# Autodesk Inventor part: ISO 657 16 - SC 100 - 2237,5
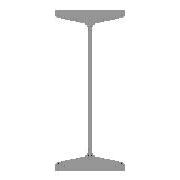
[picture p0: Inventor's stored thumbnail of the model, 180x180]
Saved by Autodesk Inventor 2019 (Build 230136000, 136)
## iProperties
_CCFamilyMember: 1
_CCFamilyDisplayName: ISO 657/16 - 1980 - Poutres en acier laminées à chaud - Partie 16: profilés en H (série métrique) - Cotes et propriétés de section
_FrameMemberDoc: Frame Member File
_Version: 15.0.0
_GetPNFromCC: 1
Created: 2018-01
Part Number: ISO 657 16 - SC 100 - 2237,5
Material: Acier, doux
Description: Poutres en acier laminées à chaud - Partie 16: profilés en H (série métrique) - Cotes et propriétés de section
Document SubType Name: Modeling
Standard: ISO
Designer: Fabian Perrée
Standard Revision: First edition 1980-02-15
Standards Organization: ISO
Language: fr-FR
Size Designation: SC 100
Categories: <MemberInstance><Categories><Category DisplayName="Profilés" InternalName="089c4875-fa83-4c05-b084-43b9cc11f5ed" Mnemonic="GRDR"><CategoryParameter DisplayName=
Stock Number: SC 100
Density: 7.85 g/cm^3
Appearance: Semi-poli
Mass: 44309.5 g
Surface Area: 12051.7 cm^2
Volume: 5644.52 cm^3
IsCustomPart: 1
G_W: 100,000 mm
G_H: 100,000 mm
+A54BEF43-0FA8-4A60-B2B6-B0B0D511939D+DETAILDECOUPE1: Angle de coupe 90,00 deg
G_L: 2237,500 mm
+E90C5402-4D48-4B32-A015-53D85A7B4022+DETAILDECOUPE4: Angle de coupe 67,38 deg
Author: Fabian Perrée
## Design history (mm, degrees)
node "Plan de départ"
node "Plan de fin"
sketch "Esquisse"
  geometry: L1 (-3, 0)-(-3, -26.266); L2 (-13.33, -38.149)-(-44.835, -42.577); L3 (-50, -48.518)-(-50, -50); L4 (-50, -50)-(0, -50); L5 (-26.5, -50)-(-26.5, -40); L6 (-61.333, 0)-(81.777, 0); L7 (0, 0)-(0, -50); L8 (0, -60)-(0, 80); L9 (3, 0)-(3, -26.266); L10 (13.33, -38.149)-(44.835, -42.577); L11 (50, -48.518)-(50, -50); L12 (50, -50)-(0, -50); L13 (-3, 0)-(0, 0); L14 (-3, 0)-(-3, 26.266); L15 (-13.33, 38.149)-(-44.835, 42.577); L16 (-50, 48.518)-(-50, 50); L17 (-50, 50)-(0, 50); L18 (50, 48.518)-(50, 50); L19 (13.33, 38.149)-(44.835, 42.577); L20 (3, 0)-(3, 26.266); L21 (50, 50)-(0, 50); L22 (0, 108)-(0, -88) reference; L23 (-89.955, 0)-(110.399, 0) reference; A1 r 6 centre (-44, 48.518) between (-50, 48.518) and (-44.835, 42.577); A2 r 6 centre (44, 48.518) between (44.835, 42.577) and (50, 48.518); A3 r 6 centre (44, -48.518) between (50, -48.518) and (44.835, -42.577); A4 r 6 centre (-44, -48.518) between (-44.835, -42.577) and (-50, -48.518); A5 r 12 centre (-15, 26.266) between (-3, 26.266) and (-13.33, 38.149); A6 r 12 centre (15, 26.266) between (13.33, 38.149) and (3, 26.266); A7 r 12 centre (15, -26.266) between (3, -26.266) and (13.33, -38.149); A8 r 12 centre (-15, -26.266) between (-13.33, -38.149) and (-3, -26.266); 14 further points
  constraints: 42 end point, 24 point on line, 17 symmetric about line, 16 point on circle, 16 tangent, 8 centre point, 6 equal radius, 4 collinear, 2 perpendicular, 12 other
  dimensions: "d1" = 10 vertical distance of L3.end L5.end (= G_T1); "d2" = 23.5 distance between parallel lines of L5 L3 (= -0.25 x G_T + 0.25 x G_W); "d3" = 3 distance between parallel lines of L1 L7 (= 0.5 x G_T); "d4" = 50 distance between parallel lines of L7 L3 (= 0.5 x G_W); "d9" = 50 distance from line of L1.start L4 (= 0.5 x G_H); "d14" = 98 deg angle of L2 L1 (= G_NG); "d15" = 6 radius of A1 (= G_ER); "d16" = 12 radius of A5 (= G_IR)
extrude "Corps" new body sketch "Esquisse" stored distance "d5" = 2237.5 (= G_L); taper "d6" = 0 deg
node "Driven Length"
  sketch "Sketch3"
    geometry: L1 (0, 0)-(10, 0) reference
    constraints: 2 end point, 1 horizontal
  workplane "Work Plane3"
  sketch "Sketch4"
    geometry: L1 (-2, 50)-(12, 50) reference; L2 (-2, 2287.5)-(12, 2287.5) reference
    dimensions: "d20" = 2237.5 distance between parallel lines of L1 L2 (derived)
node "Plan de construction4"
feature "Scission1"
node "Plan de construction7"
feature "Scission4"
body "Solid1"
other parameters: "G_W" = 100 (= G_H) [user parameter; used in 2 equation terms], "G_H" = 100 [user parameter; used in 2 equation terms], "G_T" = 6 [user parameter; used in 2 equation terms], "G_T1" = 10 [user parameter; used in 1 equation term], "G_L" = 2237.5 (= d20) [user parameter; used in 1 equation term], "G_ER" = 6 [user parameter; used in 1 equation term], "G_IR" = 12 [user parameter; used in 1 equation term], "G_NG" = 98 deg [user parameter; used in 1 equation term], "G_OFFSET_END" = -87.5 [user parameter; used in 1 equation term], "d18" = 2287.5 (= G_OFFSET_END + B_L), "B_L" = 2375 [user parameter; used in 1 equation term], "d19" = 90 deg
